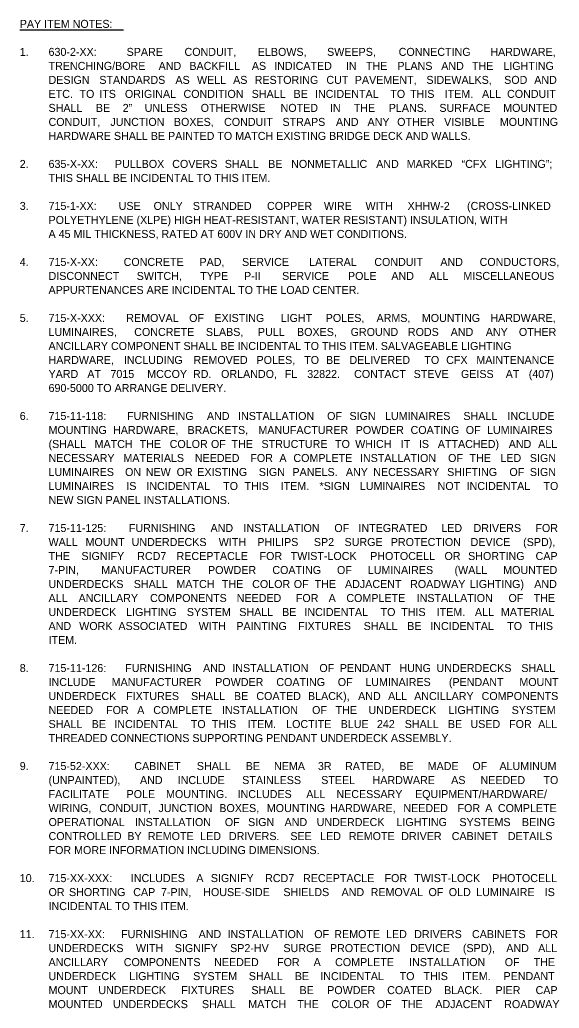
# Model space of a CAD drawing. Extents: x -55 to 2471539, y -90 to 3608906.
# Drawn here: x 27 to 499, y 2532 to 3397 of the extents above; entities that cross this region are included whole.
import ezdxf

# ---------------------------------------------------------------- set-up
doc = ezdxf.new("R2010")
doc.units = 0
doc.layers.add('XSCell', color=7, linetype='Continuous')

msp = doc.modelspace()

# ---------------------------------------------------------------- linework, layer by layer
at = {"layer": 'XSCell'}
msp.add_line((26.69, 3388.03), (117.43, 3388.03), dxfattribs=at)

# ---------------------------------------------------------------- texts
for s, p in [('PAY ITEM NOTES:', (26.68, 3389.74)), ('630-2-XX: ', (51.88, 3365.24)), ('SPARE ', (120.2, 3365.24)), ('CONDUIT, ', (170.86, 3365.24)), ('ELBOWS, ', (234.99, 3365.24)), ('SWEEPS, ', (295.62, 3365.24)), ('CONNECTING ', (358.28, 3365.24)), ('1.', (26.68, 3365.24)), ('HARDWARE, ', (438.48, 3365.24)), ('TRENCHING/BORE ', (51.88, 3352.99)), ('AND ', (148.21, 3352.99)), ('BACKFILL ', (175.12, 3352.99)), ('AS ', (229.77, 3352.99)), ('INDICATED ', (249.34, 3352.99)), ('IN ', (312.07, 3352.99)), ('THE ', (329.67, 3352.99)), ('PLANS ', (357.11, 3352.99)), ('AND ', (395.51, 3352.99)), ('THE ', (422.42, 3352.99)), ('LIGHTING ', (449.85, 3352.99)), ('DESIGN ', (51.88, 3340.74)), ('STANDARDS ', (96.32, 3340.74)), ('AS ', (162.92, 3340.74)), ('WELL ', (181.79, 3340.74)), ('AS ', (213.4, 3340.74)), ('RESTORING ', (232.27, 3340.74)), ('CUT ', (295.02, 3340.74)), ('PAVEMENT, ', (319.87, 3340.74)), ('SIDEWALKS, ', (382.51, 3340.74)), ('SOD ', (450.57, 3340.74)), ('AND ', (476.88, 3340.74)), ('ETC. ', (51.88, 3328.49)), ('TO ', (79, 3328.49)), ('ITS ', (96.3, 3328.49)), ('ORIGINAL ', (118.71, 3328.49)), ('CONDITION ', (169.95, 3328.49)), ('SHALL ', (229.63, 3328.49)), ('BE ', (266.32, 3328.49)), ('INCIDENTAL ', (285.06, 3328.49)), ('TO ', (350.93, 3328.49)), ('THIS ', (368.24, 3328.49)), ('ITEM. ', (398.5, 3328.49)), ('ALL ', (431.17, 3328.49)), ('CONDUIT ', (453.11, 3328.49)), ('SHALL ', (51.88, 3316.24)), ('BE ', (93.3, 3316.24)), ('2” ', (116.78, 3316.24)), ('UNLESS ', (135.98, 3316.24)), ('OTHERWISE ', (185.02, 3316.24)), ('NOTED ', (254.92, 3316.24)), ('IN ', (298.14, 3316.24)), ('THE ', (318.94, 3316.24)), ('PLANS. ', (349.59, 3316.24)), ('SURFACE ', (393.88, 3316.24)), ('MOUNTED ', (449.73, 3316.24)), ('CONDUIT, ', (51.88, 3303.99)), ('JUNCTION ', (105.97, 3303.99)), ('BOXES, ', (161.57, 3303.99)), ('CONDUIT ', (205.48, 3303.99)), ('STRAPS ', (256.59, 3303.99)), ('AND ', (303.36, 3303.99)), ('ANY ', (331, 3303.99)), ('OTHER ', (356.94, 3303.99)), ('VISIBLE ', (398, 3303.99)), ('MOUNTING ', (446.76, 3303.99)), ('HARDWARE SHALL BE PAINTED TO MATCH EXISTING BRIDGE DECK AND WALLS.', (51.88, 3291.74)), ('2.', (26.68, 3267.24)), ('635-X-XX: ', (51.88, 3267.24)), ('PULLBOX ', (109.95, 3267.24)), ('COVERS ', (160.1, 3267.24)), ('SHALL ', (206.08, 3267.24)), ('BE ', (244.09, 3267.24)), ('NONMETALLIC ', (264.16, 3267.24)), ('AND ', (338.57, 3267.24)), ('MARKED ', (365.28, 3267.24)), ('“CFX ', (413.35, 3267.24)), ('LIGHTING”; ', (442.76, 3267.24)), ('THIS SHALL BE INCIDENTAL TO THIS ITEM.', (51.88, 3254.99)), ('3.', (26.68, 3230.49)), ('715-1-XX: ', (51.88, 3230.49)), ('USE ', (113.22, 3230.49)), ('ONLY ', (143.8, 3230.49)), ('STRANDED ', (178.13, 3230.49)), ('COPPER ', (243.03, 3230.49)), ('WIRE ', (292.83, 3230.49)), ('WITH ', (329.22, 3230.49)), ('XHHW-2 ', (366.03, 3230.49)), ('(CROSS-LINKED ', (418.06, 3230.49)), ('POLYETHYLENE (XLPE) HIGH HEAT-RESISTANT, WATER RESISTANT) INSULATION, WITH ', (51.88, 3218.24)), ('A 45 MIL THICKNESS, RATED AT 600V IN DRY AND WET CONDITIONS.', (51.88, 3205.99)), ('4.', (26.68, 3181.49)), ('715-X-XX: ', (51.88, 3181.49)), ('CONCRETE ', (117.58, 3181.49)), ('PAD, ', (183.93, 3181.49)), ('SERVICE ', (221.18, 3181.49)), ('LATERAL ', (279.95, 3181.49)), ('CONDUIT ', (336.92, 3181.49)), ('AND ', (394.73, 3181.49)), ('CONDUCTORS, ', (429.06, 3181.49)), ('DISCONNECT ', (51.88, 3169.24)), ('SWITCH, ', (129, 3169.24)), ('TYPE ', (184.6, 3169.24)), ('P-II ', (222.95, 3169.24)), ('SERVICE ', (256.23, 3169.24)), ('POLE ', (313.89, 3169.24)), ('AND ', (351.86, 3169.24)), ('ALL ', (385.08, 3169.24)), ('MISCELLANEOUS ', (414.87, 3169.24)), ('APPURTENANCES ARE INCIDENTAL TO THE LOAD CENTER.', (51.88, 3156.99)), ('5.', (26.68, 3132.49)), ('715-X-XXX: ', (51.88, 3132.49)), ('REMOVAL ', (119.9, 3132.49)), ('OF ', (174.89, 3132.49)), ('EXISTING ', (196.97, 3132.49)), ('LIGHT ', (254.99, 3132.49)), ('POLES, ', (294.43, 3132.49)), ('ARMS, ', (338.87, 3132.49)), ('MOUNTING ', (378.54, 3132.49)), ('HARDWARE, ', (438.48, 3132.49)), ('LUMINAIRES, ', (51.88, 3120.24)), ('CONCRETE ', (126.85, 3120.24)), ('SLABS, ', (189.56, 3120.24)), ('PULL ', (235.06, 3120.24)), ('BOXES, ', (269.28, 3120.24)), ('GROUND ', (316.22, 3120.24)), ('RODS ', (366.32, 3120.24)), ('AND ', (403.79, 3120.24)), ('ANY ', (434.48, 3120.24)), ('OTHER ', (463.46, 3120.24)), ('ANCILLARY COMPONENT SHALL BE INCIDENTAL TO THIS ITEM. SALVAGEABLE LIGHTING ', (51.88, 3107.99)), ('HARDWARE, ', (51.88, 3095.74)), ('INCLUDING ', (117.79, 3095.74)), ('REMOVED ', (178.78, 3095.74)), ('POLES, ', (233.87, 3095.74)), ('TO ', (275.61, 3095.74)), ('BE ', (294.67, 3095.74)), ('DELIVERED ', (315.16, 3095.74)), ('TO ', (380.76, 3095.74)), ('CFX ', (399.82, 3095.74)), ('MAINTENANCE ', (426.23, 3095.74)), ('YARD ', (51.88, 3083.49)), ('AT ', (85.82, 3083.49)), ('7015 ', (106.03, 3083.49)), ('MCCOY ', (138.24, 3083.49)), ('RD. ', (178.25, 3083.49)), ('ORLANDO, ', (202.86, 3083.49)), ('FL ', (258.56, 3083.49)), ('32822. ', (278.26, 3083.49)), ('CONTACT ', (319.26, 3083.49)), ('STEVE ', (371.37, 3083.49)), ('GEISS ', (412.76, 3083.49)), ('AT ', (451.89, 3083.49)), ('(407) ', (472.09, 3083.49)), ('690-5000 TO ARRANGE DELIVERY.', (51.88, 3071.24)), ('6.', (26.68, 3046.74)), ('715-11-118: ', (51.88, 3046.74)), ('FURNISHING ', (120.59, 3046.74)), ('AND ', (190.46, 3046.74)), ('INSTALLATION ', (217.74, 3046.74)), ('OF ', (295.64, 3046.74)), ('SIGN ', (315.19, 3046.74)), ('LUMINAIRES ', (346.28, 3046.74)), ('SHALL ', (414.87, 3046.74)), ('INCLUDE ', (453.47, 3046.74)), ('MOUNTING ', (51.88, 3034.49)), ('HARDWARE, ', (108.34, 3034.49)), ('BRACKETS, ', (173.47, 3034.49)), ('MANUFACTURER ', (235.53, 3034.49)), ('POWDER ', (320.66, 3034.49)), ('COATING ', (368.66, 3034.49)), ('OF ', (416.96, 3034.49)), ('LUMINAIRES ', (435.57, 3034.49)), ('(SHALL ', (51.88, 3022.24)), ('MATCH ', (92.18, 3022.24)), ('THE ', (131.63, 3022.24)), ('COLOR ', (157.88, 3022.24)), ('OF ', (194, 3022.24)), ('THE ', (211.99, 3022.24)), ('STRUCTURE ', (238.25, 3022.24)), ('TO ', (302.56, 3022.24)), ('WHICH ', (320.21, 3022.24)), ('IT ', (360.1, 3022.24)), ('IS ', (375.96, 3022.24)), ('ATTACHED) ', (392.52, 3022.24)), ('AND ', (454.58, 3022.24)), ('ALL ', (480.31, 3022.24)), ('NECESSARY ', (51.88, 3009.99)), ('MATERIALS ', (117.38, 3009.99)), ('NEEDED ', (179.92, 3009.99)), ('FOR ', (228.47, 3009.99)), ('A ', (253.9, 3009.99)), ('COMPLETE ', (266.14, 3009.99)), ('INSTALLATION ', (324.41, 3009.99)), ('OF ', (401.5, 3009.99)), ('THE ', (420.23, 3009.99)), ('LED ', (447.24, 3009.99)), ('SIGN ', (473.06, 3009.99)), ('LUMINAIRES ', (51.88, 2997.74)), ('ON ', (118.83, 2997.74)), ('NEW ', (136.95, 2997.74)), ('OR ', (163.95, 2997.74)), ('EXISTING ', (182.01, 2997.74)), ('SIGN ', (235.86, 2997.74)), ('PANELS. ', (265.32, 2997.74)), ('ANY ', (312.08, 2997.74)), ('NECESSARY ', (336.02, 2997.74)), ('SHIFTING ', (400.69, 2997.74)), ('OF ', (455.16, 2997.74)), ('SIGN ', (473.06, 2997.74)), ('LUMINAIRES ', (51.88, 2985.49)), ('IS ', (119.92, 2985.49)), ('INCIDENTAL ', (137.48, 2985.49)), ('TO ', (204.7, 2985.49)), ('THIS ', (223.36, 2985.49)), ('ITEM. ', (254.98, 2985.49)), ('*SIGN ', (289, 2985.49)), ('LUMINAIRES ', (324.27, 2985.49)), ('NOT ', (392.31, 2985.49)), ('INCIDENTAL ', (417.72, 2985.49)), ('TO ', (484.95, 2985.49)), ('NEW SIGN PANEL INSTALLATIONS.', (51.88, 2973.24)), ('7.', (26.68, 2948.74)), ('715-11-125: ', (51.88, 2948.74)), ('FURNISHING ', (122.17, 2948.74)), ('AND ', (193.61, 2948.74)), ('INSTALLATION ', (222.47, 2948.74)), ('OF ', (301.95, 2948.74)), ('INTEGRATED ', (323.07, 2948.74)), ('LED ', (395.56, 2948.74)), ('DRIVERS ', (423.77, 2948.74)), ('FOR ', (477.92, 2948.74)), ('WALL ', (51.88, 2936.49)), ('MOUNT ', (84.21, 2936.49)), ('UNDERDECKS ', (124.57, 2936.49)), ('WITH ', (200.79, 2936.49)), ('PHILIPS ', (234.56, 2936.49)), ('SP2 ', (284.05, 2936.49)), ('SURGE ', (310.91, 2936.49)), ('PROTECTION ', (351.37, 2936.49)), ('DEVICE ', (421.19, 2936.49)), ('(SPD), ', (467.17, 2936.49)), ('THE ', (51.88, 2924.24)), ('SIGNIFY ', (80.66, 2924.24)), ('RCD7 ', (129.46, 2924.24)), ('RECEPTACLE ', (163.91, 2924.24)), ('FOR ', (236.51, 2924.24)), ('TWIST-LOCK ', (263.72, 2924.24)), ('PHOTOCELL ', (333.31, 2924.24)), ('OR ', (398.35, 2924.24)), ('SHORTING ', (419.03, 2924.24)), ('CAP ', (478.04, 2924.24)), ('7-PIN, ', (51.88, 2911.99)), ('MANUFACTURER ', (98.01, 2911.99)), ('POWDER ', (191.42, 2911.99)), ('COATING ', (247.71, 2911.99)), ('OF ', (304.29, 2911.99)), ('LUMINAIRES ', (331.19, 2911.99)), ('(WALL ', (407.13, 2911.99)), ('MOUNTED ', (449.73, 2911.99)), ('UNDERDECKS ', (51.88, 2899.74)), ('SHALL ', (126.46, 2899.74)), ('MATCH ', (163.78, 2899.74)), ('THE ', (203.52, 2899.74)), ('COLOR ', (230.07, 2899.74)), ('OF ', (266.47, 2899.74)), ('THE ', (284.75, 2899.74)), ('ADJACENT ', (311.29, 2899.74)), ('ROADWAY ', (368.28, 2899.74)), ('LIGHTING) ', (420.58, 2899.74)), ('AND ', (476.88, 2899.74)), ('ALL ', (51.88, 2887.49)), ('ANCILLARY ', (78.17, 2887.49)), ('COMPONENTS ', (140.72, 2887.49)), ('NEEDED ', (216.49, 2887.49)), ('FOR ', (268.29, 2887.49)), ('A ', (296.98, 2887.49)), ('COMPLETE ', (312.48, 2887.49)), ('INSTALLATION ', (374.01, 2887.49)), ('OF ', (454.36, 2887.49)), ('THE ', (476.35, 2887.49)), ('UNDERDECK ', (51.88, 2875.24)), ('LIGHTING ', (119.72, 2875.24)), ('SYSTEM ', (172.89, 2875.24)), ('SHALL ', (218.79, 2875.24)), ('BE ', (256.25, 2875.24)), ('INCIDENTAL ', (275.77, 2875.24)), ('TO ', (342.42, 2875.24)), ('THIS ', (360.5, 2875.24)), ('ITEM. ', (391.54, 2875.24)), ('ALL ', (424.98, 2875.24)), ('MATERIAL ', (447.7, 2875.24)), ('AND ', (51.88, 2862.99)), ('WORK ', (78.7, 2862.99)), ('ASSOCIATED ', (113.03, 2862.99)), ('WITH ', (183.25, 2862.99)), ('PAINTING ', (216.2, 2862.99)), ('FIXTURES ', (270.23, 2862.99)), ('SHALL ', (327.61, 2862.99)), ('BE ', (365.74, 2862.99)), ('INCIDENTAL ', (385.93, 2862.99)), ('TO ', (453.24, 2862.99)), ('THIS ', (471.99, 2862.99)), ('ITEM. ', (51.88, 2850.74)), ('8.', (26.68, 2826.24)), ('715-11-126: ', (51.88, 2826.24)), ('FURNISHING ', (118.91, 2826.24)), ('AND ', (187.08, 2826.24)), ('INSTALLATION ', (212.67, 2826.24)), ('OF ', (288.88, 2826.24)), ('PENDANT ', (306.74, 2826.24)), ('HUNG ', (358.91, 2826.24)), ('UNDERDECKS ', (391.4, 2826.24)), ('SHALL ', (465.57, 2826.24)), ('INCLUDE ', (51.88, 2813.99)), ('MANUFACTURER ', (107.12, 2813.99)), ('POWDER ', (197.72, 2813.99)), ('COATING ', (251.2, 2813.99)), ('OF ', (304.97, 2813.99)), ('LUMINAIRES ', (329.06, 2813.99)), ('(PENDANT ', (402.2, 2813.99)), ('MOUNT ', (463.87, 2813.99)), ('UNDERDECK ', (51.88, 2801.74)), ('FIXTURES ', (119.79, 2801.74)), ('SHALL ', (176.58, 2801.74)), ('BE ', (214.12, 2801.74)), ('COATED ', (233.71, 2801.74)), ('BLACK), ', (278.91, 2801.74)), ('AND ', (322.78, 2801.74)), ('ALL ', (349.01, 2801.74)), ('ANCILLARY ', (371.8, 2801.74)), ('COMPONENTS ', (430.84, 2801.74)), ('NEEDED ', (51.88, 2789.49)), ('FOR ', (102.23, 2789.49)), ('A ', (129.47, 2789.49)), ('COMPLETE ', (143.52, 2789.49)), ('INSTALLATION ', (203.6, 2789.49)), ('OF ', (282.5, 2789.49)), ('THE ', (303.04, 2789.49)), ('UNDERDECK ', (331.86, 2789.49)), ('LIGHTING ', (401.83, 2789.49)), ('SYSTEM ', (457.13, 2789.49)), ('SHALL ', (51.88, 2777.24)), ('BE ', (89.63, 2777.24)), ('INCIDENTAL ', (109.43, 2777.24)), ('TO ', (176.37, 2777.24)), ('THIS ', (194.74, 2777.24)), ('ITEM. ', (226.07, 2777.24)), ('LOCTITE ', (259.8, 2777.24)), ('BLUE ', (307.5, 2777.24)), ('242 ', (339.23, 2777.24)), ('SHALL ', (363.54, 2777.24)), ('BE ', (401.3, 2777.24)), ('USED ', (421.1, 2777.24)), ('FOR ', (454.91, 2777.24)), ('ALL ', (480.31, 2777.24)), ('THREADED CONNECTIONS SUPPORTING PENDANT UNDERDECK ASSEMBLY.', (51.88, 2764.99)), ('9.', (26.68, 2740.49)), ('715-52-XXX: ', (51.88, 2740.49)), ('CABINET ', (126.9, 2740.49)), ('SHALL ', (181.66, 2740.49)), ('BE ', (224.4, 2740.49)), ('NEMA ', (249.19, 2740.49)), ('3R ', (287.59, 2740.49)), ('RATED, ', (311.35, 2740.49)), ('BE ', (358.85, 2740.49)), ('MADE ', (383.63, 2740.49)), ('OF ', (422.77, 2740.49)), ('ALUMINUM ', (446.46, 2740.49)), ('(UNPAINTED), ', (51.88, 2728.24)), ('AND ', (131.91, 2728.24)), ('INCLUDE ', (164.91, 2728.24)), ('STAINLESS ', (221.34, 2728.24)), ('STEEL ', (290.48, 2728.24)), ('HARDWARE ', (335.39, 2728.24)), ('AS ', (404.2, 2728.24)), ('NEEDED ', (429.87, 2728.24)), ('TO ', (484.95, 2728.24)), ('FACILITATE ', (51.88, 2715.99)), ('POLE ', (120.17, 2715.99)), ('MOUNTING. ', (154.71, 2715.99)), ('INCLUDES ', (217.31, 2715.99)), ('ALL ', (277.41, 2715.99)), ('NECESSARY ', (303.78, 2715.99)), ('EQUIPMENT/HARDWARE/ ', (372.6, 2715.99)), ('WIRING, ', (51.88, 2703.74)), ('CONDUIT, ', (96.31, 2703.74)), ('JUNCTION ', (148.07, 2703.74)), ('BOXES, ', (201.32, 2703.74)), ('MOUNTING ', (242.88, 2703.74)), ('HARDWARE, ', (298.3, 2703.74)), ('NEEDED ', (362.39, 2703.74)), ('FOR ', (409.76, 2703.74)), ('A ', (434.02, 2703.74)), ('COMPLETE ', (445.09, 2703.74)), ('OPERATIONAL ', (51.88, 2691.49)), ('INSTALLATION ', (127.45, 2691.49)), ('OF ', (206.15, 2691.49)), ('SIGN ', (226.51, 2691.49)), ('AND ', (258.41, 2691.49)), ('UNDERDECK ', (286.5, 2691.49)), ('LIGHTING ', (356.28, 2691.49)), ('SYSTEMS ', (411.4, 2691.49)), ('BEING ', (466.12, 2691.49)), ('CONTROLLED ', (51.88, 2679.24)), ('BY ', (120.82, 2679.24)), ('REMOTE ', (138.79, 2679.24)), ('LED ', (184.59, 2679.24)), ('DRIVERS. ', (209.72, 2679.24)), ('SEE ', (263.47, 2679.24)), ('LED ', (289.55, 2679.24)), ('REMOTE ', (314.68, 2679.24)), ('DRIVER ', (360.49, 2679.24)), ('CABINET ', (404.66, 2679.24)), ('DETAILS ', (453.78, 2679.24)), ('FOR MORE INFORMATION INCLUDING DIMENSIONS. ', (51.88, 2666.99)), ('10.', (26.68, 2642.49)), ('715-XX-XXX: ', (51.88, 2642.49)), ('INCLUDES ', (123.88, 2642.49)), ('A ', (181.16, 2642.49)), ('SIGNIFY ', (193.9, 2642.49)), ('RCD7 ', (241.4, 2642.49)), ('RECEPTACLE ', (274.57, 2642.49)), ('FOR ', (345.88, 2642.49)), ('TWIST-LOCK ', (371.8, 2642.49)), ('PHOTOCELL ', (440.1, 2642.49)), ('OR ', (51.88, 2630.24)), ('SHORTING ', (69.76, 2630.24)), ('CAP ', (125.98, 2630.24)), ('7-PIN, ', (150.28, 2630.24)), ('HOUSE-SIDE ', (187.24, 2630.24)), ('SHIELDS ', (257.4, 2630.24)), ('AND ', (308.26, 2630.24)), ('REMOVAL ', (333.73, 2630.24)), ('OF ', (384.36, 2630.24)), ('OLD ', (402.09, 2630.24)), ('LUMINAIRE ', (426.16, 2630.24)), ('IS ', (486.05, 2630.24)), ('INCIDENTAL TO THIS ITEM.', (51.88, 2617.99)), ('11.', (26.68, 2593.49)), ('715-XX-XX: ', (51.88, 2593.49)), ('FURNISHING ', (115.36, 2593.49)), ('AND ', (183.21, 2593.49)), ('INSTALLATION ', (208.49, 2593.49)), ('OF ', (284.38, 2593.49)), ('REMOTE ', (301.92, 2593.49)), ('LED ', (347.22, 2593.49)), ('DRIVERS ', (371.85, 2593.49)), ('CABINETS ', (422.41, 2593.49)), ('FOR ', (477.92, 2593.49)), ('UNDERDECKS ', (51.88, 2581.24)), ('WITH ', (128.34, 2581.24)), ('SIGNIFY ', (162.36, 2581.24)), ('SP2-HV ', (210.78, 2581.24)), ('SURGE ', (257.42, 2581.24)), ('PROTECTION ', (298.13, 2581.24)), ('DEVICE ', (368.2, 2581.24)), ('(SPD), ', (414.43, 2581.24)), ('AND ', (452.42, 2581.24)), ('ALL ', (480.31, 2581.24)), ('ANCILLARY ', (51.88, 2568.99)), ('COMPONENTS ', (117.71, 2568.99)), ('NEEDED ', (196.76, 2568.99)), ('FOR ', (251.85, 2568.99)), ('A ', (283.83, 2568.99)), ('COMPLETE ', (302.62, 2568.99)), ('INSTALLATION ', (367.44, 2568.99)), ('OF ', (451.07, 2568.99)), ('THE ', (476.35, 2568.99)), ('UNDERDECK ', (51.88, 2556.74)), ('LIGHTING ', (122.5, 2556.74)), ('SYSTEM ', (178.46, 2556.74)), ('SHALL ', (227.13, 2556.74)), ('BE ', (267.38, 2556.74)), ('INCIDENTAL ', (289.68, 2556.74)), ('TO ', (359.1, 2556.74)), ('THIS ', (379.97, 2556.74)), ('ITEM. ', (413.79, 2556.74)), ('PENDANT ', (450.01, 2556.74)), ('MOUNT ', (51.88, 2544.49)), ('UNDERDECK ', (95.44, 2544.49)), ('FIXTURES ', (167.96, 2544.49)), ('SHALL ', (229.37, 2544.49)), ('BE ', (271.51, 2544.49)), ('POWDER ', (295.72, 2544.49)), ('COATED ', (348.21, 2544.49)), ('BLACK. ', (398.02, 2544.49)), ('PIER ', (442.95, 2544.49)), ('CAP ', (478.04, 2544.49)), ('MOUNTED ', (51.88, 2532.24)), ('UNDERDECKS ', (108.27, 2532.24)), ('SHALL ', (186.1, 2532.24)), ('MATCH ', (226.66, 2532.24)), ('THE ', (269.64, 2532.24)), ('COLOR ', (299.42, 2532.24)), ('OF ', (339.07, 2532.24)), ('THE ', (360.58, 2532.24)), ('ADJACENT ', (390.36, 2532.24)), ('ROADWAY ', (450.6, 2532.24))]:
    msp.add_text(s, height=7, dxfattribs=at).set_placement(p)

doc.saveas('drawing.dxf')
